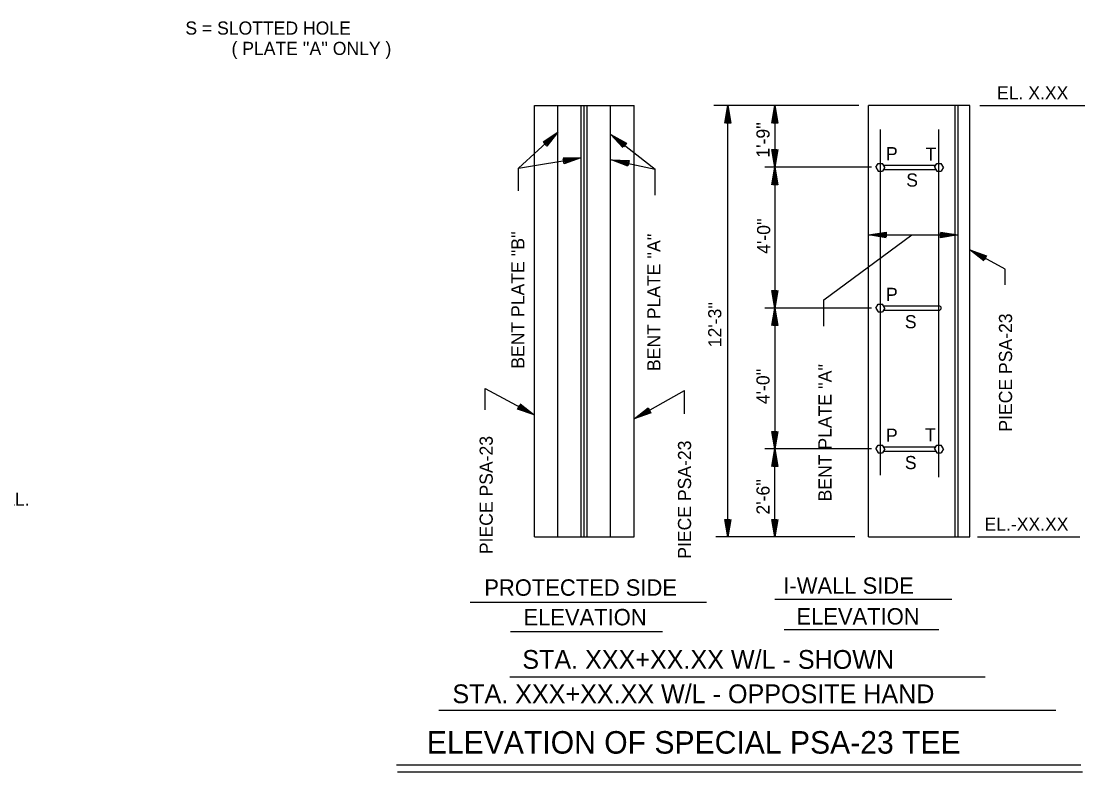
# Model space of a CAD drawing. Extents: x 22369.6 to 22384.3, y 22369.6 to 22381.8.
# Drawn here: x 22376.535 to 22380.313, y 22372.384 to 22375.048 of the extents above; entities that cross this region are included whole.
import ezdxf

# ---------------------------------------------------------------- set-up
doc = ezdxf.new("R2010")
doc.units = 0
for name, color, linetype in [('Level 1', 7, 'Continuous'), ('Level 10', 7, 'Continuous'), ('Level 3', 7, 'Continuous'), ('Level 4', 7, 'Continuous'), ('Level 7', 7, 'Continuous')]:
    doc.layers.add(name, color=color, linetype=linetype)

msp = doc.modelspace()

# ---------------------------------------------------------------- linework, layer by layer
at = {"layer": 'Level 1'}
for p, q in [((22379.5101, 22374.7483), (22378.995, 22374.7483)), ((22379.0451, 22373.217), (22379.0451, 22374.7483)), ((22379.0451, 22374.7483), (22379.0451, 22374.7483)), ((22379.2118, 22374.7483), (22379.2118, 22374.5295)), ((22379.2118, 22374.7483), (22379.2118, 22374.7483)), ((22379.9399, 22374.7483), (22380.3129, 22374.7483)), ((22379.0451, 22374.7309), (22379.0451, 22374.7309)), ((22379.2118, 22374.7309), (22379.2118, 22374.7309)), ((22378.3012, 22374.526), (22378.4414, 22374.6535)), ((22378.4286, 22374.6418), (22378.4286, 22374.6418)), ((22378.4414, 22374.6535), (22378.4414, 22374.6535)), ((22378.6292, 22374.6457), (22378.787, 22374.5229)), ((22378.6292, 22374.6457), (22378.6292, 22374.6457)), ((22378.6429, 22374.635), (22378.6429, 22374.635)), ((22379.5868, 22373.4368), (22379.5868, 22374.6633)), ((22379.7951, 22373.4288), (22379.7951, 22374.6633)), ((22378.3012, 22374.526), (22378.5232, 22374.5623)), ((22378.5061, 22374.5595), (22378.5061, 22374.5595)), ((22378.5232, 22374.5623), (22378.5232, 22374.5623)), ((22378.6312, 22374.5562), (22378.787, 22374.5229)), ((22378.6312, 22374.5562), (22378.6312, 22374.5562)), ((22378.6481, 22374.5526), (22378.6481, 22374.5526)), ((22378.3012, 22374.4454), (22378.3012, 22374.526)), ((22378.787, 22374.4309), (22378.787, 22374.5229)), ((22379.5549, 22374.5295), (22379.1764, 22374.5295)), ((22379.2118, 22374.5469), (22379.2118, 22374.5469)), ((22379.2118, 22374.5295), (22379.2118, 22374.0295)), ((22379.2118, 22374.5295), (22379.2118, 22374.5295)), ((22379.2118, 22374.5295), (22379.2118, 22374.5295)), ((22379.5711, 22374.5295), (22379.5789, 22374.5432)), ((22379.5711, 22374.5295), (22379.5789, 22374.5159)), ((22379.5789, 22374.5432), (22379.5946, 22374.5432)), ((22379.5789, 22374.5159), (22379.5946, 22374.5159)), ((22379.6025, 22374.5295), (22379.5946, 22374.5432)), ((22379.6025, 22374.5295), (22379.5946, 22374.5159)), ((22379.5979, 22374.5373), (22379.7839, 22374.5373)), ((22379.5979, 22374.5217), (22379.7839, 22374.5217)), ((22379.7794, 22374.5295), (22379.7873, 22374.5432)), ((22379.7794, 22374.5295), (22379.7873, 22374.5159)), ((22379.7873, 22374.5432), (22379.8029, 22374.5432)), ((22379.7873, 22374.5159), (22379.8029, 22374.5159)), ((22379.7951, 22374.5295), (22379.7951, 22374.5446)), ((22379.8108, 22374.5295), (22379.8029, 22374.5432)), ((22379.8108, 22374.5295), (22379.8029, 22374.5159)), ((22379.2118, 22374.5122), (22379.2118, 22374.5122)), ((22379.3858, 22374.0593), (22379.6983, 22374.2892)), ((22379.5451, 22374.2892), (22379.8628, 22374.2892)), ((22379.5451, 22374.2892), (22379.5451, 22374.2892)), ((22379.5624, 22374.2892), (22379.5624, 22374.2892)), ((22379.8455, 22374.2892), (22379.8455, 22374.2892)), ((22379.8628, 22374.2892), (22379.8628, 22374.2892)), ((22380.03, 22374.1673), (22379.9045, 22374.2364)), ((22379.9045, 22374.2364), (22379.9045, 22374.2364)), ((22379.9197, 22374.228), (22379.9197, 22374.228)), ((22380.03, 22374.1115), (22380.03, 22374.1673)), ((22379.3858, 22373.9652), (22379.3858, 22374.0593)), ((22379.5549, 22374.0295), (22379.1764, 22374.0295)), ((22379.2118, 22374.0469), (22379.2118, 22374.0469)), ((22379.2118, 22374.0295), (22379.2118, 22373.5295)), ((22379.2118, 22374.0295), (22379.2118, 22374.0295)), ((22379.2118, 22374.0295), (22379.2118, 22374.0295)), ((22379.5711, 22374.0295), (22379.5789, 22374.0432)), ((22379.5711, 22374.0295), (22379.5789, 22374.0159)), ((22379.5789, 22374.0432), (22379.5946, 22374.0432)), ((22379.6025, 22374.0295), (22379.5946, 22374.0432)), ((22379.6025, 22374.0295), (22379.5946, 22374.0159)), ((22379.5979, 22374.0373), (22379.7951, 22374.0373)), ((22379.5979, 22374.0217), (22379.7951, 22374.0217)), ((22379.2118, 22374.0122), (22379.2118, 22374.0122)), ((22379.5789, 22374.0159), (22379.5946, 22374.0159)), ((22378.1827, 22373.6688), (22378.1827, 22373.7441)), ((22378.1827, 22373.7441), (22378.3574, 22373.6505)), ((22378.7127, 22373.6363), (22378.8913, 22373.7367)), ((22378.8913, 22373.6546), (22378.8913, 22373.7367)), ((22378.3421, 22373.6587), (22378.3421, 22373.6587)), ((22378.3574, 22373.6505), (22378.3574, 22373.6505)), ((22378.7278, 22373.6448), (22378.7278, 22373.6448)), ((22378.7127, 22373.6363), (22378.7127, 22373.6363)), ((22379.2118, 22373.5469), (22379.2118, 22373.5469)), ((22379.5711, 22373.5295), (22379.5789, 22373.5432)), ((22379.5789, 22373.5432), (22379.5946, 22373.5432)), ((22379.6025, 22373.5295), (22379.5946, 22373.5432)), ((22379.5979, 22373.5373), (22379.7839, 22373.5373)), ((22379.7794, 22373.5295), (22379.7873, 22373.5432)), ((22379.7873, 22373.5432), (22379.8029, 22373.5432)), ((22379.8108, 22373.5295), (22379.8029, 22373.5432)), ((22379.5549, 22373.5295), (22379.1764, 22373.5295)), ((22379.2118, 22373.217), (22379.2118, 22373.5295)), ((22379.2118, 22373.5295), (22379.2118, 22373.5295)), ((22379.2118, 22373.5295), (22379.2118, 22373.5295)), ((22379.2118, 22373.5122), (22379.2118, 22373.5122)), ((22379.5711, 22373.5295), (22379.5789, 22373.5159)), ((22379.5789, 22373.5159), (22379.5946, 22373.5159)), ((22379.6025, 22373.5295), (22379.5946, 22373.5159)), ((22379.5979, 22373.5217), (22379.7839, 22373.5217)), ((22379.7794, 22373.5295), (22379.7873, 22373.5159)), ((22379.7873, 22373.5159), (22379.8029, 22373.5159)), ((22379.8108, 22373.5295), (22379.8029, 22373.5159)), ((22379.0451, 22373.2344), (22379.0451, 22373.2344)), ((22379.2118, 22373.2344), (22379.2118, 22373.2344)), ((22379.4965, 22373.217), (22379.0022, 22373.217)), ((22379.0451, 22373.217), (22379.0451, 22373.217)), ((22379.2118, 22373.217), (22379.2118, 22373.217)), ((22379.9314, 22373.217), (22380.296, 22373.217))]:
    msp.add_line(p, q, dxfattribs=at)
for points in [[(22379.0348, 22374.6859), (22379.0451, 22374.7483), (22379.0554, 22374.6859), (22379.0378, 22374.6859), (22379.0451, 22374.7309), (22379.0521, 22374.6886), (22379.0408, 22374.6886), (22379.0451, 22374.7143), (22379.0488, 22374.6913), (22379.0441, 22374.6913), (22379.0451, 22374.6969)], [(22379.2014, 22374.6859), (22379.2118, 22374.7483), (22379.2221, 22374.6859), (22379.2044, 22374.6859), (22379.2118, 22374.7309), (22379.2188, 22374.6886), (22379.2074, 22374.6886), (22379.2118, 22374.7143), (22379.2154, 22374.6913), (22379.2108, 22374.6913), (22379.2118, 22374.6969)], [(22378.3884, 22374.6192), (22378.4414, 22374.6535), (22378.4023, 22374.6039), (22378.3904, 22374.617), (22378.4286, 22374.6418), (22378.402, 22374.6082), (22378.3944, 22374.6166), (22378.4163, 22374.6306), (22378.4017, 22374.6124), (22378.3986, 22374.6159), (22378.4034, 22374.619)], [(22378.6721, 22374.5992), (22378.6292, 22374.6457), (22378.6848, 22374.6155), (22378.6739, 22374.6016), (22378.6429, 22374.635), (22378.6806, 22374.6145), (22378.6737, 22374.6056), (22378.6561, 22374.6248), (22378.6765, 22374.6136), (22378.6736, 22374.6099), (22378.6697, 22374.6141)], [(22379.2221, 22374.5919), (22379.2118, 22374.5295), (22379.2014, 22374.5919), (22379.2191, 22374.5919), (22379.2118, 22374.5469), (22379.2048, 22374.5892), (22379.2161, 22374.5892), (22379.2118, 22374.5635), (22379.2081, 22374.5865), (22379.2128, 22374.5865), (22379.2118, 22374.5809)], [(22378.4601, 22374.5624), (22378.5232, 22374.5623), (22378.4634, 22374.542), (22378.4605, 22374.5595), (22378.5061, 22374.5595), (22378.4655, 22374.5458), (22378.4637, 22374.5569), (22378.4897, 22374.5568), (22378.4676, 22374.5495), (22378.4668, 22374.5541), (22378.4726, 22374.554)], [(22378.69, 22374.5331), (22378.6312, 22374.5562), (22378.6943, 22374.5533), (22378.6906, 22374.536), (22378.6481, 22374.5526), (22378.691, 22374.5506), (22378.6886, 22374.5395), (22378.6644, 22374.5491), (22378.6877, 22374.5479), (22378.6867, 22374.5433), (22378.6814, 22374.5455)], [(22379.2014, 22374.4672), (22379.2118, 22374.5295), (22379.2221, 22374.4672), (22379.2044, 22374.4672), (22379.2118, 22374.5122), (22379.2188, 22374.4699), (22379.2074, 22374.4699), (22379.2118, 22374.4955), (22379.2154, 22374.4725), (22379.2108, 22374.4725), (22379.2118, 22374.4782)], [(22379.6074, 22374.2789), (22379.5451, 22374.2892), (22379.6074, 22374.2995), (22379.6074, 22374.2819), (22379.5624, 22374.2892), (22379.6048, 22374.2962), (22379.6048, 22374.2849), (22379.5791, 22374.2892), (22379.6021, 22374.2929), (22379.6021, 22374.2882), (22379.5964, 22374.2892)], [(22379.8005, 22374.2995), (22379.8628, 22374.2892), (22379.8005, 22374.2789), (22379.8005, 22374.2965), (22379.8455, 22374.2892), (22379.8031, 22374.2822), (22379.8031, 22374.2935), (22379.8288, 22374.2892), (22379.8058, 22374.2855), (22379.8058, 22374.2902), (22379.8115, 22374.2892)], [(22379.9541, 22374.1973), (22379.9045, 22374.2364), (22379.9641, 22374.2154), (22379.9556, 22374.1999), (22379.9197, 22374.228), (22379.9601, 22374.2137), (22379.9547, 22374.2038), (22379.9343, 22374.22), (22379.9562, 22374.2121), (22379.9539, 22374.208), (22379.9494, 22374.2116)], [(22379.2221, 22374.0919), (22379.2118, 22374.0295), (22379.2014, 22374.0919), (22379.2191, 22374.0919), (22379.2118, 22374.0469), (22379.2048, 22374.0892), (22379.2161, 22374.0892), (22379.2118, 22374.0635), (22379.2081, 22374.0865), (22379.2128, 22374.0865), (22379.2118, 22374.0809)], [(22379.2014, 22373.9672), (22379.2118, 22374.0295), (22379.2221, 22373.9672), (22379.2044, 22373.9672), (22379.2118, 22374.0122), (22379.2188, 22373.9699), (22379.2074, 22373.9699), (22379.2118, 22373.9955), (22379.2154, 22373.9725), (22379.2108, 22373.9725), (22379.2118, 22373.9782)], [(22378.3073, 22373.6891), (22378.3574, 22373.6505), (22378.2976, 22373.6708), (22378.3059, 22373.6864), (22378.3421, 22373.6587), (22378.3015, 22373.6725), (22378.3068, 22373.6825), (22378.3274, 22373.6666), (22378.3054, 22373.6742), (22378.3076, 22373.6783), (22378.3121, 22373.6747)], [(22378.7721, 22373.6578), (22378.7127, 22373.6363), (22378.7619, 22373.6758), (22378.7706, 22373.6604), (22378.7278, 22373.6448), (22378.7612, 22373.6716), (22378.7668, 22373.6617), (22378.7423, 22373.6529), (22378.7605, 22373.6674), (22378.7628, 22373.6633), (22378.7574, 22373.6614)], [(22379.2221, 22373.5919), (22379.2118, 22373.5295), (22379.2014, 22373.5919), (22379.2191, 22373.5919), (22379.2118, 22373.5469), (22379.2048, 22373.5892), (22379.2161, 22373.5892), (22379.2118, 22373.5635), (22379.2081, 22373.5865), (22379.2128, 22373.5865), (22379.2118, 22373.5809)], [(22379.2014, 22373.4672), (22379.2118, 22373.5295), (22379.2221, 22373.4672), (22379.2044, 22373.4672), (22379.2118, 22373.5122), (22379.2188, 22373.4699), (22379.2074, 22373.4699), (22379.2118, 22373.4955), (22379.2154, 22373.4725), (22379.2108, 22373.4725), (22379.2118, 22373.4782)], [(22379.0554, 22373.2794), (22379.0451, 22373.217), (22379.0348, 22373.2794), (22379.0524, 22373.2794), (22379.0451, 22373.2344), (22379.0381, 22373.2767), (22379.0494, 22373.2767), (22379.0451, 22373.251), (22379.0414, 22373.274), (22379.0461, 22373.274), (22379.0451, 22373.2684)], [(22379.2221, 22373.2794), (22379.2118, 22373.217), (22379.2014, 22373.2794), (22379.2191, 22373.2794), (22379.2118, 22373.2344), (22379.2048, 22373.2767), (22379.2161, 22373.2767), (22379.2118, 22373.251), (22379.2081, 22373.274), (22379.2128, 22373.274), (22379.2118, 22373.2684)]]:
    msp.add_lwpolyline(points, dxfattribs=at)
msp.add_arc((22379.7951, 22374.0295), 0.00781, 270, 90, dxfattribs=at)
at = {"layer": 'Level 10'}
for p, q in [((22378.1293, 22372.9854), (22378.9693, 22372.9854)), ((22379.2118, 22372.9958), (22379.8412, 22372.9958)), ((22379.2453, 22372.8884), (22379.794, 22372.8884)), ((22378.2732, 22372.8815), (22378.8126, 22372.8815)), ((22378.271, 22372.7205), (22379.9591, 22372.7205)), ((22378.0186, 22372.6022), (22380.2097, 22372.6022)), ((22380.2986, 22372.4069), (22377.8673, 22372.4069)), ((22377.8714, 22372.3836), (22380.3045, 22372.3836))]:
    msp.add_line(p, q, dxfattribs=at)
at = {"layer": 'Level 7'}
for p, q in [((22378.3576, 22373.217), (22378.3576, 22374.7483)), ((22378.3576, 22374.7483), (22378.7118, 22374.7483)), ((22378.4409, 22373.217), (22378.4409, 22374.7483)), ((22378.5243, 22373.217), (22378.5243, 22374.7483)), ((22378.5347, 22373.217), (22378.5347, 22374.7483)), ((22378.5451, 22373.217), (22378.5451, 22374.7483)), ((22378.6284, 22373.217), (22378.6284, 22374.7483)), ((22378.7118, 22373.217), (22378.7118, 22374.7483)), ((22379.5451, 22373.217), (22379.5451, 22374.7483)), ((22379.9045, 22374.7483), (22379.5451, 22374.7483)), ((22379.8524, 22373.217), (22379.8524, 22374.7483)), ((22379.8628, 22373.217), (22379.8628, 22374.7483)), ((22379.9045, 22373.217), (22379.9045, 22374.7483)), ((22378.3576, 22373.217), (22378.7118, 22373.217)), ((22379.5451, 22373.217), (22379.9045, 22373.217))]:
    msp.add_line(p, q, dxfattribs=at)

# ---------------------------------------------------------------- texts
at = {"layer": 'Level 3'}
for s, height, p in [('PROTECTED SIDE', 0.058302, (22378.1798, 22373.0082)), ('I-WALL SIDE', 0.058302, (22379.2422, 22373.0152)), ('ELEVATION', 0.0583, (22379.2887, 22372.906)), ('ELEVATION', 0.0583, (22378.3189, 22372.9032)), ('STA. XXX+XX.XX W/L - SHOWN', 0.066698, (22378.3148, 22372.7488)), ('STA. XXX+XX.XX W/L - OPPOSITE HAND', 0.066698, (22378.0665, 22372.6268)), ('ELEVATION OF SPECIAL PSA-23 TEE', 0.08, (22377.9756, 22372.4477))]:
    msp.add_text(s, height=height, dxfattribs=at).set_placement(p)
at = {"layer": 'Level 4'}
for s, height, p in [('S = SLOTTED HOLE', 0.046661, (22377.1177, 22375.0002)), ("( PLATE ''A'' ONLY )", 0.046661, (22377.2817, 22374.928)), ('EL. X.XX', 0.04666, (22380.0014, 22374.7704)), ('P', 0.0467, (22379.6069, 22374.5542)), ('T', 0.0467, (22379.7474, 22374.5525)), ('S', 0.0467, (22379.6788, 22374.4607)), ('P', 0.0467, (22379.6069, 22374.0547)), ('S', 0.0467, (22379.6738, 22373.9577)), ('P', 0.0467, (22379.6069, 22373.5547)), ('T', 0.0467, (22379.7457, 22373.5564)), ('S', 0.0467, (22379.6738, 22373.4577)), ('CONTRACTING OFFICER REPRESENTATIVE FOR APPROVAL.', 0.046667, (22374.7158, 22373.3281)), ('EL.-XX.XX', 0.04666, (22379.9569, 22373.2393))]:
    msp.add_text(s, height=height, dxfattribs=at).set_placement(p)
for s, height, p in [("1'-9''", 0.04666, (22379.1932, 22374.5636)), ("4'-0''", 0.04666, (22379.1954, 22374.2221)), ("BENT PLATE ''B''", 0.046661, (22378.3221, 22373.8142)), ("BENT PLATE ''A''", 0.046661, (22378.8053, 22373.8061)), ("12'-3''", 0.04666, (22379.0218, 22373.8905)), ('PIECE PSA-23', 0.046661, (22380.0548, 22373.5909)), ("4'-0''", 0.04666, (22379.1932, 22373.6886)), ("BENT PLATE ''A''", 0.046661, (22379.4133, 22373.3433)), ('PIECE PSA-23', 0.046661, (22378.2097, 22373.1559)), ('PIECE PSA-23', 0.046661, (22378.9144, 22373.1396)), ("2'-6''", 0.04666, (22379.1932, 22373.2965))]:
    msp.add_text(s, height=height, rotation=90, dxfattribs=at).set_placement(p)

doc.saveas('drawing.dxf')
